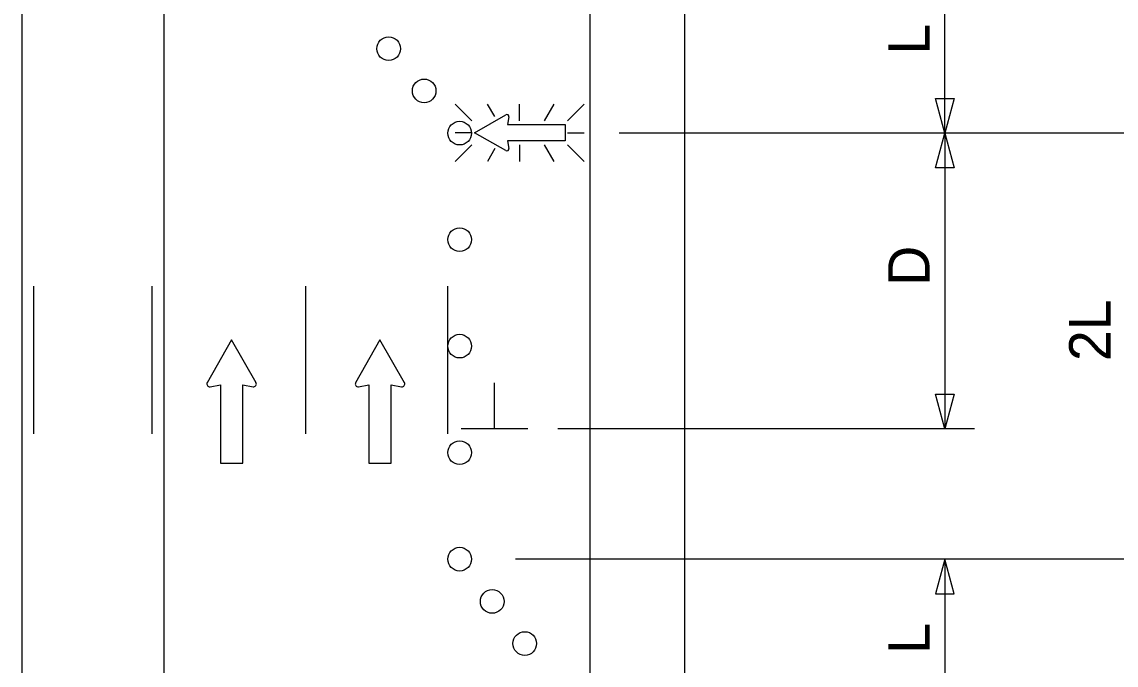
# Model space of a CAD drawing. Extents: x 16038 to 19504, y 5920 to 8321.
# Drawn here: x 17058.3 to 17243.3, y 7442.1 to 7550.9 of the extents above; entities that cross this region are included whole.
import ezdxf

# ---------------------------------------------------------------- set-up
doc = ezdxf.new("R2010")
doc.units = 0
for name, color, linetype in [('ALI_LEGAL_EX', 7, 'Continuous'), ('MT_SCRATCH_LEVEL_E', 7, 'Continuous'), ('PAVT_EDGE_EX', 7, 'Continuous'), ('TRAFFIC_SIGNS_PR', 7, 'Continuous'), ('TYPICAL_TEXT_DIMEN_PR', 7, 'Continuous')]:
    doc.layers.add(name, color=color, linetype=linetype)

msp = doc.modelspace()

# ---------------------------------------------------------------- linework, layer by layer
at = {"layer": 'ALI_LEGAL_EX'}
for points in [[(17060.3, 7481.21), (17060.3, 7506.21)], [(17080.3, 7481.21), (17080.3, 7506.21)], [(17106.3, 7481.21), (17106.3, 7506.21)], [(17130.3, 7481.21), (17130.3, 7506.21)]]:
    msp.add_lwpolyline(points, dxfattribs=at)
at = {"layer": 'MT_SCRATCH_LEVEL_E'}
for p, q in [((17093.74, 7497.12), (17089.63, 7489.88)), ((17093.74, 7497.12), (17089.63, 7489.88)), ((17097.88, 7489.88), (17093.74, 7497.12)), ((17097.88, 7489.88), (17093.74, 7497.12)), ((17118.83, 7497.12), (17114.72, 7489.88)), ((17118.83, 7497.12), (17114.72, 7489.88)), ((17122.97, 7489.88), (17118.83, 7497.12)), ((17122.97, 7489.88), (17118.83, 7497.12)), ((17090.11, 7489.2), (17091.89, 7489.51)), ((17090.11, 7489.2), (17091.89, 7489.51)), ((17091.89, 7489.51), (17091.89, 7476.26)), ((17091.89, 7489.51), (17091.89, 7476.26)), ((17095.63, 7476.26), (17095.63, 7489.51)), ((17095.63, 7489.51), (17097.4, 7489.2)), ((17095.63, 7476.26), (17095.63, 7489.51)), ((17095.63, 7489.51), (17097.4, 7489.2)), ((17115.2, 7489.2), (17116.97, 7489.51)), ((17115.2, 7489.2), (17116.97, 7489.51)), ((17116.97, 7489.51), (17116.97, 7476.26)), ((17116.97, 7489.51), (17116.97, 7476.26)), ((17120.72, 7476.26), (17120.72, 7489.51)), ((17120.72, 7489.51), (17122.49, 7489.2)), ((17120.72, 7476.26), (17120.72, 7489.51)), ((17120.72, 7489.51), (17122.49, 7489.2)), ((17091.89, 7476.26), (17095.63, 7476.26)), ((17091.89, 7476.26), (17095.63, 7476.26)), ((17116.97, 7476.26), (17120.72, 7476.26)), ((17116.97, 7476.26), (17120.72, 7476.26))]:
    msp.add_line(p, q, dxfattribs=at)
for centre, start, end in [((17090.03, 7489.66), 150.4248, 279.9638), ((17090.03, 7489.66), 150.4248, 279.9638), ((17097.47, 7489.66), 260.0362, 29.7731), ((17097.47, 7489.66), 260.0362, 29.7731), ((17115.12, 7489.66), 150.4248, 279.9638), ((17115.12, 7489.66), 150.4248, 279.9638), ((17122.56, 7489.66), 260.0362, 29.7731), ((17122.56, 7489.66), 260.0362, 29.7731)]:
    msp.add_arc(centre, 0.463, start, end, dxfattribs=at)
at = {"layer": 'PAVT_EDGE_EX'}
for p, q in [((17154.3, 8211.37), (17154.3, 7379.53)), ((17170.3, 8211.37), (17170.3, 7379.53)), ((17058.3, 7652.9), (17058.3, 7379.53)), ((17082.3, 7625.58), (17082.3, 7379.53))]:
    msp.add_line(p, q, dxfattribs=at)
at = {"layer": 'TRAFFIC_SIGNS_PR'}
for p, q in [((17131.54, 7536.97), (17134.35, 7534.15)), ((17136.97, 7536.97), (17138.18, 7534.88)), ((17142.44, 7534.15), (17142.44, 7536.97)), ((17148.23, 7536.97), (17146.6, 7534.15)), ((17150.53, 7534.15), (17153.35, 7536.97)), ((17134.35, 7532.12), (17131.54, 7532.12)), ((17150.53, 7532.12), (17153.35, 7532.12)), ((17131.54, 7527.27), (17134.35, 7530.08)), ((17142.44, 7530.08), (17142.44, 7527.26)), ((17146.58, 7530.08), (17148.2, 7527.26)), ((17150.53, 7530.08), (17153.35, 7527.26)), ((17138.26, 7529.45), (17137, 7527.26))]:
    msp.add_line(p, q, dxfattribs=at)
for points in [[(17140.11, 7529.1), (17134.8, 7532.12), (17140.11, 7535.16)], [(17140.61, 7534.8), (17140.38, 7533.5), (17150.11, 7533.5), (17150.11, 7530.76), (17140.38, 7530.76), (17140.62, 7529.45)]]:
    msp.add_lwpolyline(points, dxfattribs=at)
for centre in [(17120.3, 7546.33), (17126.3, 7539.19), (17132.3, 7532.05), (17132.3, 7514.05), (17132.3, 7496.05), (17132.3, 7478.05), (17132.3, 7460.05), (17137.8, 7452.91), (17143.3, 7445.79)]:
    msp.add_circle(centre, 2, dxfattribs=at)
for centre, start, end in [((17140.28, 7534.86), 350.0407, 118.5167), ((17140.28, 7529.4), 241.1084, 9.2692)]:
    msp.add_arc(centre, 0.341, start, end, dxfattribs=at)
at = {"layer": 'TYPICAL_TEXT_DIMEN_PR'}
for p, q in [((17214.3, 7532.05), (17214.3, 7560.61)), ((17214.3, 7532.05), (17212.73, 7537.91)), ((17212.73, 7537.91), (17214.3, 7537.91)), ((17214.3, 7537.91), (17215.87, 7537.91)), ((17215.87, 7537.91), (17214.3, 7532.05)), ((17249.88, 7532.05), (17159.27, 7532.05)), ((17212.73, 7526.18), (17214.3, 7532.05)), ((17214.3, 7532.05), (17214.3, 7482.05)), ((17214.3, 7532.05), (17215.87, 7526.18)), ((17214.3, 7526.18), (17212.73, 7526.18)), ((17215.87, 7526.18), (17214.3, 7526.18)), ((17138.19, 7482.05), (17138.19, 7489.83)), ((17214.3, 7482.05), (17212.73, 7487.91)), ((17212.73, 7487.91), (17214.3, 7487.91)), ((17214.3, 7487.91), (17215.87, 7487.91)), ((17215.87, 7487.91), (17214.3, 7482.05)), ((17143.82, 7482.05), (17132.57, 7482.05)), ((17219.3, 7482.05), (17148.9, 7482.05)), ((17219.3, 7482.05), (17193.3, 7482.05)), ((17249.88, 7460.05), (17141.76, 7460.05)), ((17214.3, 7460.05), (17212.73, 7454.18)), ((17214.3, 7460.05), (17214.3, 7429.53)), ((17215.87, 7454.18), (17214.3, 7460.05)), ((17212.73, 7454.18), (17214.3, 7454.18)), ((17214.3, 7454.18), (17215.87, 7454.18))]:
    msp.add_line(p, q, dxfattribs=at)

# ---------------------------------------------------------------- texts
for s, p in [('L', (17211.74, 7545.35)), ('D', (17211.74, 7506.26)), ('2L', (17242.32, 7493.53)), ('L', (17211.74, 7444.06))]:
    msp.add_text(s, height=7, rotation=90, dxfattribs=at).set_placement(p)

doc.saveas('drawing.dxf')
